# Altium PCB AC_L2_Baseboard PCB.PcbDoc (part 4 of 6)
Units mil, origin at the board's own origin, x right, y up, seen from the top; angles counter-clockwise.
Board outline 7290 x 7055 mil, 4 copper layers (Top Layer, Layer 1, Layer 2, Bottom Layer), stack 70.356 mil thick; 510 components, 285 nets, 1364 pads, 522 vias.
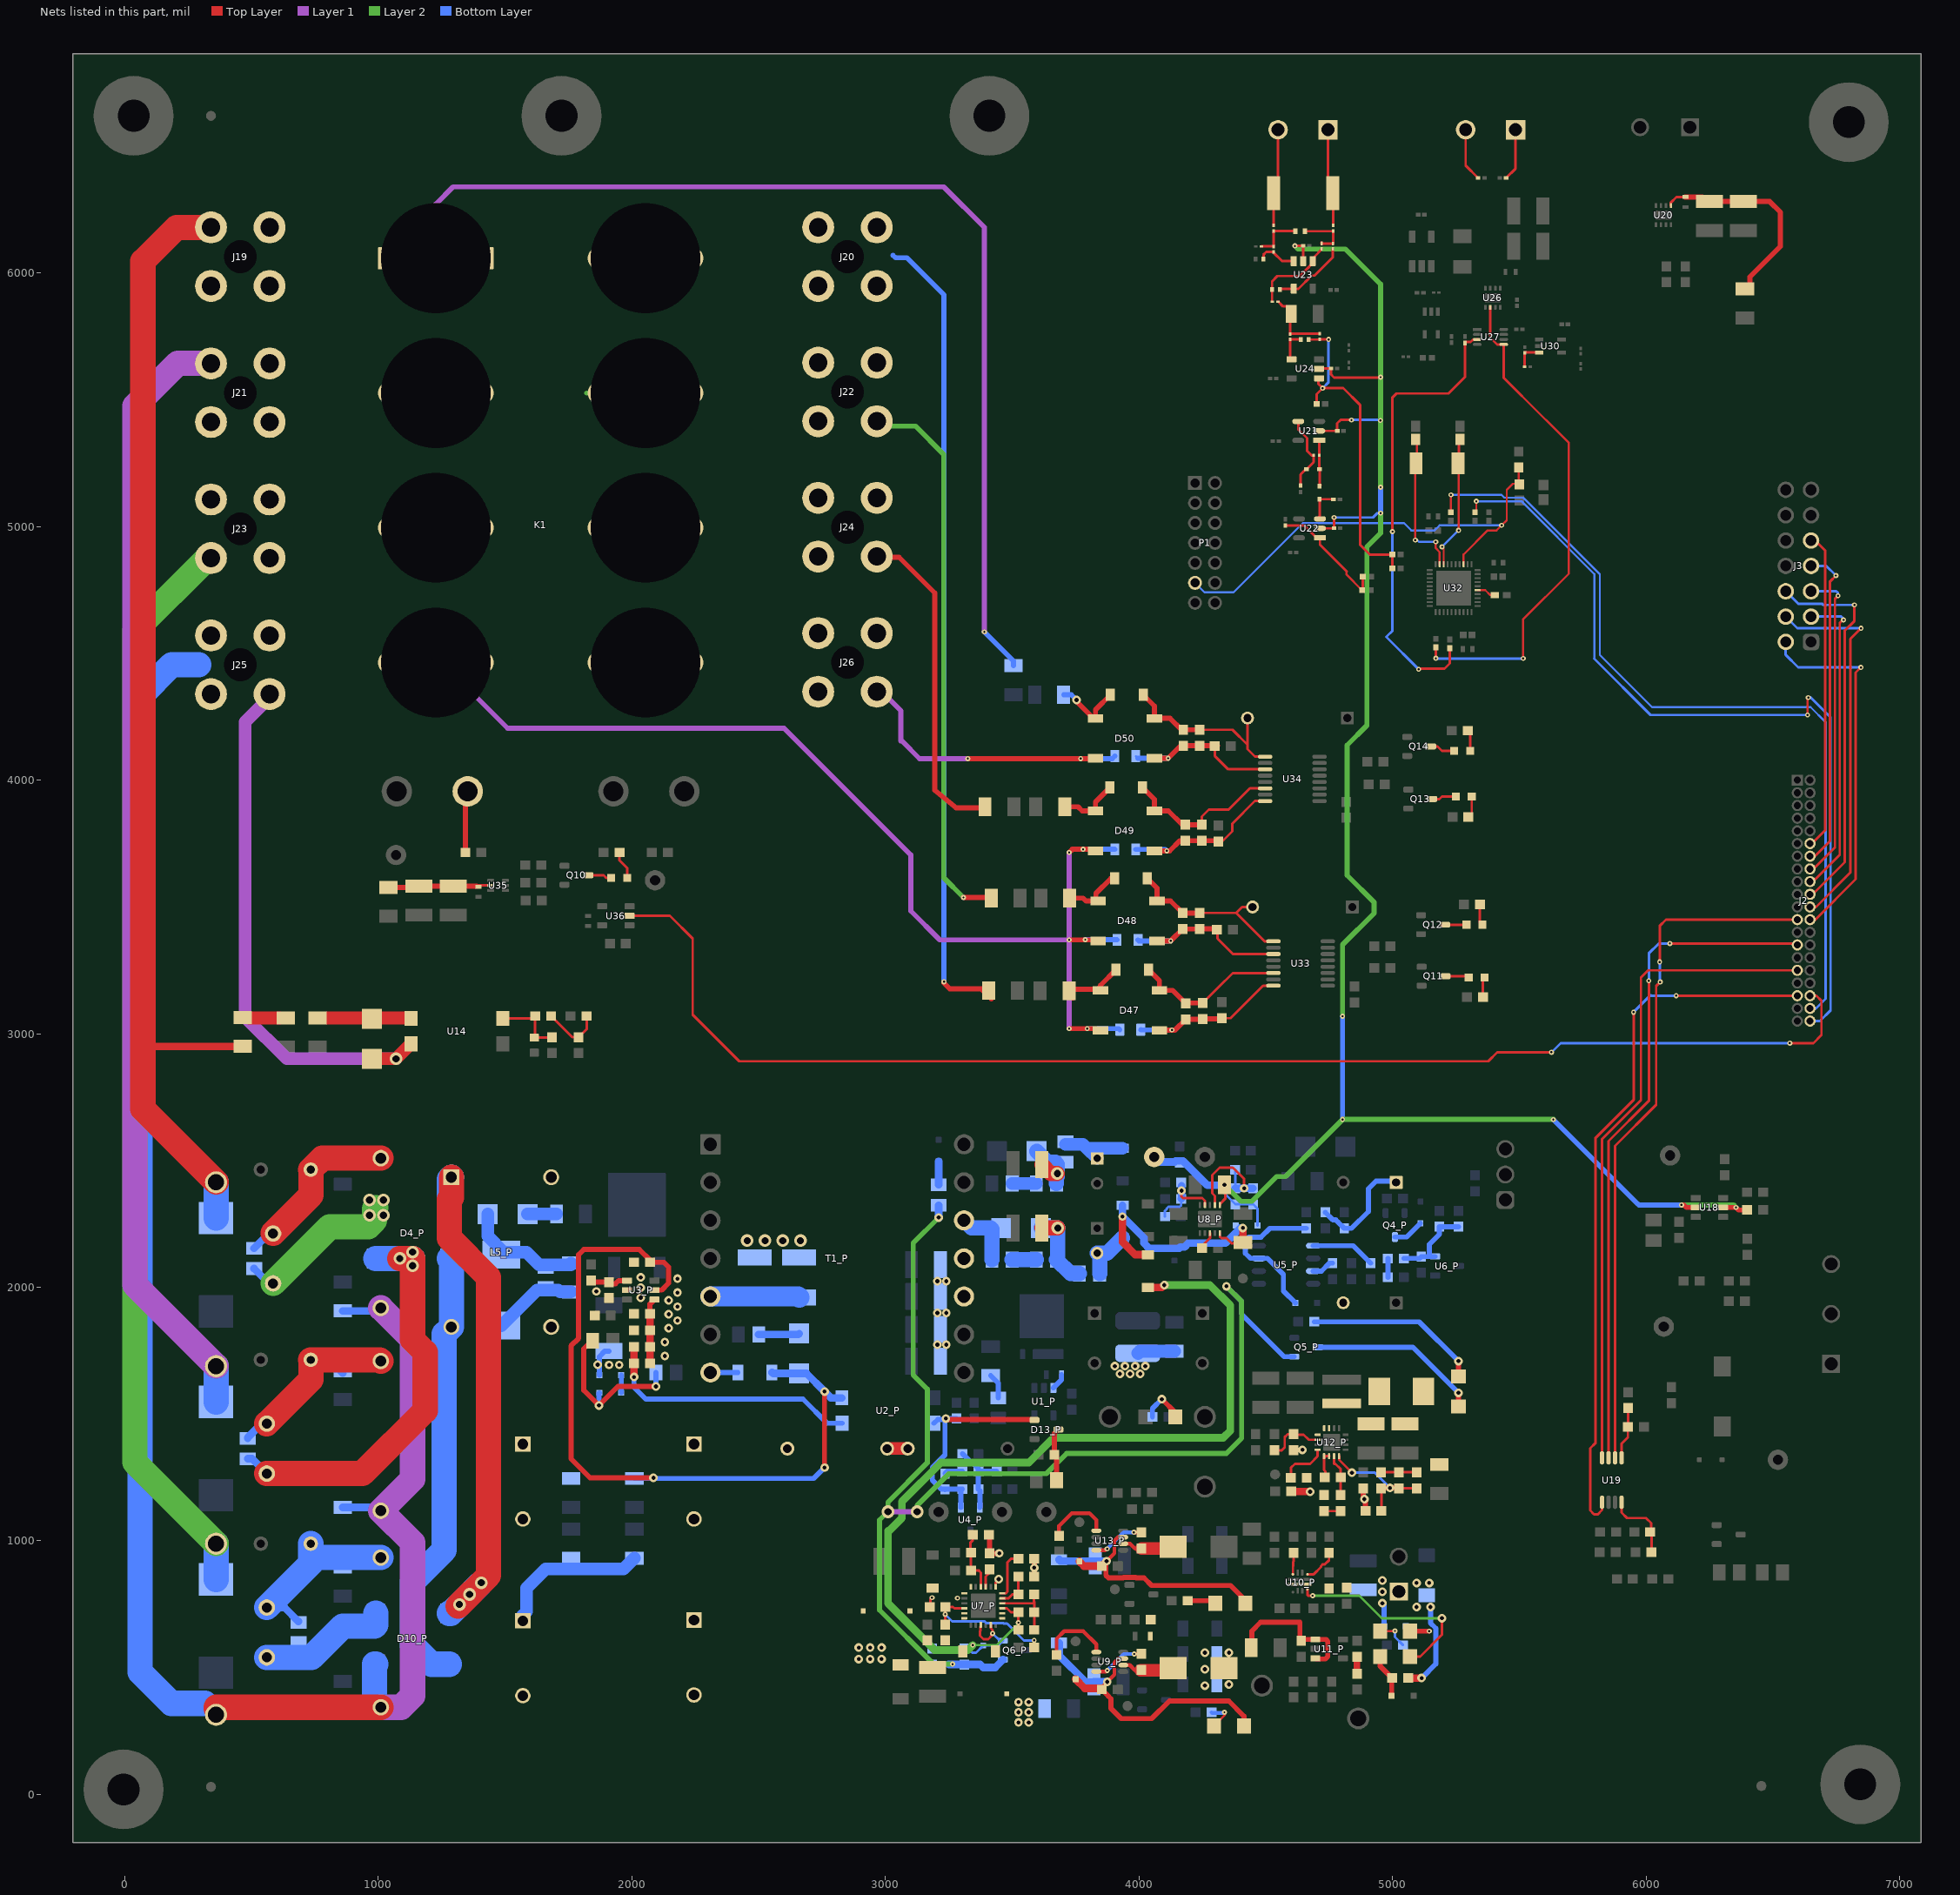
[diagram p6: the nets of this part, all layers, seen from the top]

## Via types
v1: diameter 34, hole 16, Top Layer to Bottom Layer, tented both sides, 231 vias
v2: diameter 20, hole 8, Top Layer to Bottom Layer, tented both sides, 209 vias
v3: diameter 50, hole 28, Top Layer to Bottom Layer, tented both sides, 48 vias
v4: diameter 19.68, hole 7.87, Top Layer to Bottom Layer, 29 vias
v5: diameter 24, hole 12, Top Layer to Bottom Layer, 5 vias

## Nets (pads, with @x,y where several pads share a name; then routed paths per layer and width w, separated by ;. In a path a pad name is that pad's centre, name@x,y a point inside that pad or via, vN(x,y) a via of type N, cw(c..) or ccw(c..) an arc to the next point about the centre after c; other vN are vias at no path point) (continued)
-12Va: C58_P.2 C59_P.1 C61_P.1 C100.1 C117.2 C118.2 C119.2 C120.2 D24_P.1 R54_P.2 TP12_P.1 U8_P.6 U18.2 U18.5 U21.2 U22.2 U23.2 U24.2 | length 7930.8
  Top Layer w10: U8_P.6@4319.37,2324.12 4319.88,2324.12 4320,2324 4320,2329 4340,2349 4340,2401.09 v1(4337.09,2404) ; v2(4615,6107) C117.2@4647.83,6106.96 ; C117.2@4647.83,6106.96 4647.91,6106.87 4647.91,6047.22 U23.2@4648,6047.13 ; U24.2@4707.79,5623.4 C118.2@4757.59,5623.4 4757.59,5600.41 4770,5588 4952,5588 v2(4953,5589) ; U21.2@4710.95,5377.4 C119.2@4782.61,5377.4 4782.08,5377.93 4782.08,5407.08 4795.44,5420.44 v2(4838,5420.44) ; U22.2@4713.91,4992.98 4766.95,4992.98 4769.57,4995.59 v2(4769.56,5035.96) ; v2(6140,2325) v2@6149,2325
  Top Layer w20: v2@6149,2325 6159,2315 U18.5@6195.87,2315 ; U18.2@6304.13,2315 v2(6355,2315) 6365,2305 C100.1@6398.5,2305
  Layer 2 w20: v1(4337.09,2404) 4402.09,2339 4445,2339 4543,2437 4578,2437 v2(4803,2662) v2@5635,2662 ; v2(4615,6107) 4627.5,6094.5 4814.5,6094.5 4953,5956 v2(4953,5589) v2(4953,5155) ; v2(4803,3069) 4803,3351 4928,3476 4928,3518 4821,3625 4821,4138 4899,4216 4899,4920 4953,4974 v2(4953,5053) ; v2(6140,2325) 6345,2325 v2(6355,2315)
  Bottom Layer w10: v1(4337.09,2404) 4337.09,2402.54 4337.09,2370.42 R54_P.2@4380,2327.5 C58_P.2@4450,2327.5 4468.31,2309.2 D24_P.1@4468.31,2244 ; v2(4769.56,5035.96) 4922.96,5035.96 4940,5053 v2(4953,5053) ; v2(4838,5420.44) 4950.56,5420.44 v2(4952.47,5418.53)
  Bottom Layer w20: v2(4803,2662) v2(4803,3069) ; v2(4953,5053) v2(4953,5155) ; v2(5634.5,2661.5) 5967,2329 ; 5968,2329 5972,2325 v2(6140,2325)
  Bottom Layer w30: TP12_P.1@4060,2514 4080,2494 4140,2494 4145,2499 4173.27,2499 4269.72,2402.54 v1@4337.09,2402.54
-14V: C53_P.1 D5_P.2 D8_P.2 D24_P.2 U8_P.5 | length 1007.3
  Top Layer w10: U8_P.5@4319.37,2213.88 4319.37,2199.63 4325,2194 4345,2194 4365,2174 C53_P.1@4407.09,2174 ; C53_P.1@4410,2176.91 C53_P.1@4410,2189
  Top Layer w30: v1(3935,2279) 3935,2179 3985.53,2128.47 D5_P.2@4035,2128.47 ; C53_P.1@4410,2189 v1(4410,2234)
  Bottom Layer w30: D8_P.2@3935,2323.47 v1(3935,2279) 3936.08,2279 4020,2195.08 4020,2174 4040,2154 4158.61,2154 4163.48,2158.87 4179.87,2158.87 4195,2174 4341.02,2174 4401.02,2234 v1(4410,2234)
-14V_INV: C52_P.1 C54_P.1 D5_P.1 D22_P.2 R51_P.2 U7_P.15 | length 3473.2
  Top Layer w10: U7_P.15@3460.8,734.16 3479.82,734.16 3494.98,719 R51_P.2@3524.5,719 v2(3524.5,677.54) C52_P.1@3524.5,649
  Top Layer w30: D5_P.1@4035,1999.53 4035.53,1999 4090,1999 v1(4100,2009)
  Layer 2 w10: v2(3345,589) 3440,589 3524.5,673.5 v2(3524.5,677.54)
  Layer 2 w30: v2(3345,589) 3325,569 3195,569 3010,754 3010,1040 3015,1040 3065,1090 3065,1155 3219,1309 3566.02,1309 3664.02,1407 4333,1407 4360,1434 4360,1929 4280,2009 v1(4100,2009)
AC_Sense+: J16.1 R139.1 R143.2 | length 385.6
  Top Layer w10: J16.1@4745.56,6564.96 4745.56,6333.54 R143.2@4763.98,6315.12 4765.56,6313.54 R139.1@4765.56,6187.68
AC_Sense-: J16.2 R143.1 R145.1 | length 384.8
  Top Layer w10: R145.1@4530.56,6187.68 4530.56,6313.98 R143.1@4531.7,6315.12 4548.71,6332.13 J16.2@4548.71,6564.96
AC_SENSING_A: C130.2 R135.2 R144.1 R175.1 R178.1 U24.1 | length 1323.5
  Top Layer w10: C130.2@4669.79,5737.81 4712.73,5737.81 4712.81,5737.89 4712.89,5738 v2(4748,5738) ; R144.1@4700.72,5483.4 4700.72,5522.12 v2(4724.56,5545.96) ; U24.1@4707.79,5586 4707.79,5562.73 v2(4724.56,5545.96) ; R178.1@4998.94,4834.72 R175.1@4998.94,4889.72 4911.28,4889.72 4872,4929 4872,5480 4806.04,5545.96 v2(4724.56,5545.96)
  Bottom Layer w10: v2(4724.56,5545.96) 4748,5569.4 v2(4748,5738)
AC_SENSING_B: R138.2 R179.1 R180.1 U22.1 | length 489.9
  Top Layer w8: 4819,4823.23 4819,4810.27 R180.1@4880.27,4749 R180.1@4882.17,4747.1
  Top Layer w10: R138.2@4578.04,5003.76 4652.48,5003.76 4700.66,4955.57 U22.1@4713.91,4955.57 4713.91,4928.31 4819,4823.23 ; R180.1@4882.17,4747.1 R179.1@4882.17,4803
ADC_SPI_CS: J2.35 U19.1 | length 2800.9
  Top Layer w10: U19.1@5826.61,1152.4 5826.61,1121.61 5810,1105 5795,1105 5780,1120 5780,1365 5800,1385 5800,2588 5951,2739 v2(5951,3085) ; v2(6119,3150) J2.35@6597,3150
  Bottom Layer w10: v2(5951,3085) 6018,3152 6020,3150 v2(6119,3150)
ADC_SPI_DIN: J2.23 U19.6 | length 2722.4
  Top Layer w10: U19.6@5877.8,1327.6 5877.8,2557.8 6040,2720 6040,3188 v2(6056,3204) ; v2@6054,3286 6054,3425 6079,3450 J2.23@6597,3450
  Bottom Layer w10: v2(6054,3283) 6054,3206 v2(6056,3204)
ADC_SPI_DOUT: J2.27 U19.7 | length 2665.8
  Top Layer w10: U19.7@5852.2,1327.6 5852.2,2576.2 6011,2735 6011,3212 v2(6011,3209) ; v2(6094,3356) 6591,3356 J2.27@6597,3350
  Bottom Layer w10: v2(6011,3209) 6011,3317 6050,3356 v2(6094,3356)
ADC_SPI_SCLK: J2.31 U19.8 | length 2586.5
  Top Layer w10: U19.8@5826.61,1327.6 5826.61,2584.61 5980,2738 5980,3222 6008,3250 J2.31@6597,3250
AGND1: C49_P.1 C55_P.2 C56_P.1 C57_P.2 C62_P.2 D25_P.2 NT1_P.2 Q6_P.2 R48_P.2 R57_P.1 U7_P.9 U7_P.11 U7_P.19 | length 768.9
  Top Layer w10: C55_P.2@3174.5,739 3177,739 3177,769 v2(3184,776) ; U7_P.9@3376,669.04 U7_P.9@3376.16,669.2 3376.16,662.31 3375.5,661.65 3375.5,646.85 3373.13,644.47 3373.13,625.53 3386.53,612.13 3405.47,612.13 3418.87,625.53 3418.87,630.87 v2(3423,635) 3423,647.62 3417.42,653.21 3417.42,653.58 3415.53,655.47 U7_P.11@3415.53,669.2 ; U7_P.19@3435.21,818.8 3435.21,837.21 v1(3447,849)
  Top Layer w20: R48_P.2@3407.5,1024 3411,1020.5 C56_P.1@3411,950.5 3448.5,950.5 v1(3449,951) ; C49_P.1@3587.5,859 C57_P.2@3587.5,929
  Bottom Layer w10: C62_P.2@3185,575.5 R57_P.1@3311,575.5 3326.16,575.5 3335.53,566.13 3335.87,566.13 3343,559 3357.69,559 D25_P.2@3386,587.31 3444.66,587.31 Q6_P.2@3463.76,606.4 3451.6,606.4 v2(3423,635)
  other v1: 3587,894
  other v2: 3284.21,774.5
AGND2: C82_P.1 C91_P.2 C92_P.2 C93_P.1 NT2_P.1 R77_P.1 R78_P.1 R201_P.1 U12_P.5 U12_P.6 | length 306.9
  Top Layer w10: C82_P.1@4610,1357.5 4643.5,1357.5 v1(4645,1359) ; C91_P.2@4732.2,1249 4735,1251.8 4735,1274 4730,1279 4730.41,1326.99 4737.3,1333.88 U12_P.6@4750.16,1333.88
  Top Layer w20: R78_P.1@4885,1207.5 4885,1169 4893.5,1160.5 R77_P.1@4893.5,1119
  Top Layer w30: R201_P.1@4600,1195 4674,1195 v1(4675,1194)
  other v1: 4889.25,1164.75
AM62_R_ENABLE: J2.36 U36.2 | length 5345.9
  Top Layer w10: U36.2@1990.61,3465.04 2149.96,3465.04 2240,3375 2240,3075 2423.5,2891.5 5377.5,2891.5 5413,2927 v2(5627,2927) ; v2(6567,2963) 6660,2963 6692.08,2995.08 6692.08,3129.92 6672,3150 J2.36@6647,3150
  Bottom Layer w10: v2(5627,2927) 5663,2963 v2(6567,2963)
EM_GPIO1: J2.12 J3.9 | length 1231.2
  Top Layer w10: J2.12@6647,3750 6654,3750 6706,3802 6706,4906 J3.9@6673,4939
EM_M0_EN_GPIO: J2.14 J3.7 | length 1274.1
  Top Layer w10: J2.14@6647,3700 6666,3700 6726,3760 6726,4784 v2(6749,4807)
  Bottom Layer w10: J3.7@6651,4845 6711,4845 v2(6749,4807)
EM_P1_A_GPIO: J2.18 J3.3 | length 1230.6
  Top Layer w10: J2.18@6647,3600 6658,3600 6764,3706 6764,4620 6776,4632 v2(6779,4632)
  Bottom Layer w10: J3.3@6651,4645 6770,4645 6779,4636 v2(6779,4632)
EM_P2_R_GPIO: J2.16 J3.5 | length 1250.1
  Top Layer w10: J2.16@6647,3650 6660,3650 6745,3735 6745,4715 v2(6757,4727)
  Bottom Layer w10: J3.5@6651,4745 6750,4745 6757,4738 v2(6757,4727)
EM_UART_GPIO: J2.20 J3.6 | length 1513.3
  Top Layer w10: J2.20@6647,3550 6653,3556 6664,3556 6784,3676 6784,4590 6822,4628 v2(6822,4691)
  Bottom Layer w10: J3.6@6551,4745 6600,4696 6694,4696 6699,4691 v2(6822,4691)
EM_UART_RX: J2.22 J3.4 | length 1511.8
  Top Layer w10: J2.22@6647,3500 6670,3500 6806,3636 6806,4557 v2(6848,4599)
  Bottom Layer w10: J3.4@6551,4645 6597,4599 v2(6848,4599)
EM_UART_TX: J2.24 J3.2 | length 1457.9
  Top Layer w10: J2.24@6647,3450 6668,3450 6827,3609 6827,4424 v2(6847.5,4444.5)
  Bottom Layer w10: J3.2@6551,4545 6551,4494 6600.5,4444.5 v2(6847.5,4444.5)
FF_Q+: R184.1 U26.6 U27.5 | length 1991.4
  Top Layer w8: 5510.56,5514.96 5695.56,5329.96 5695.56,4814.96 5515.56,4634.96 v2(5515.56,4479.96)
  Top Layer w10: v2(5171.03,4480.43) R184.1@5171.03,4523.94 ; U26.6@5385.87,5864.96 5385.87,5745.13 5412.57,5718.43 U27.5@5438.76,5718.43 5438.76,5586.76 5510.56,5514.96
  Bottom Layer w10: v2(5171.03,4480.43) 5171.5,4479.96 v2(5515.56,4479.96)
FF_Q-: R154.1 R187.1 U27.3 | length 1835.8
  Top Layer w10: v2(5000,4980) 5000,5509.4 5015.56,5524.96 5220.56,5524.96 5285.56,5589.96 5285.56,5725.13 5288.45,5728.02 5308.45,5728.02 5318.22,5737.8 5334.03,5737.8 U27.3@5334.36,5738.12 ; v2(5103.06,4437.46) 5105.56,4439.96 5205.56,4439.96 5226.03,4460.43 R187.1@5226.03,4520.67
  Bottom Layer w10: v2(5000,4980) 5000,4589.41 4975.56,4564.96 v2@5103.03,4437.49
FluxGate+: J17.1 R151.2 | length 205.4
  Top Layer w10: R151.2@5448.35,6374.96 5485.56,6412.17 J17.1@5485.56,6564.96
FluxGate-: J17.2 R152.2 | length 210.3
  Top Layer w10: J17.2@5288.71,6564.96 5288.71,6424.02 R152.2@5337.76,6374.96
Fly_ON: C62_P.1 D25_P.1 Q5_P.1 Q6_P.1 R56_P.2 R57_P.2 | length 4978.5
  Layer 1 w20: v3(3010,1115) v3(3125,1115)
  Layer 2 w20: v3(3125,1115) 3125,1140 3250,1265 3635,1265 3715,1345 4345,1345 4405,1405 4405,1944 v1(4345,2004) ; v1(3210,2275.02) 3110,2175.02 3110,1654 3165,1599 3165,1308.07 3010,1153.07 v3(3010,1115) 2977.13,1082.13 2977.13,726.87 3190,514 v2(3265,514)
  Bottom Layer w20: C62_P.1@3185,512.5 3247.5,512.5 3248.99,514 ; v1(4345,2004) 4405,1944 4405,1894 4572.4,1726.6 Q5_P.1@4612.76,1726.6
  Bottom Layer w30: v1(3210,2275.02) R56_P.2@3210,2324 ; 3248.99,514 3250.49,512.5 R57_P.2@3311,512.5 3374.19,512.5 D25_P.1@3386,500.69 3432.85,500.69 Q6_P.1@3463.76,531.6
GND: C2_P.2 C6_P.2 C7_P.2 C16_P.2 C17_P.2 C30_P.2 C32_P.2 C34_P.2 C200_P.1 D16_P.1 L5_P.3 R31_P.1 R35_P.1 R40_P.1 T1_P.7 U3_P.5 | length 228.1
  Bottom Layer w20: D16_P.1@1871.69,1654 1871.69,1726.69 1893.45,1748.45 R35_P.1@1910,1748.45 ; T1_P.7@2310,1664 C30_P.2@2418.07,1664
  other v1: 1910,1694 1950,1694 1864.88,1694.83 2130,1729 2130,1784 2145,1839 2180,1869 2145,1894 2180,1924 2145,1949 2035,1959 2180,1979 1860,1984 2035,1999 2180,2034 2035,2039
  other v3: 2455,2184 2525,2184 2595,2184 2665,2184
"GPIO AC Fault": J2.40 R189.1 | length 3341.5
  Top Layer w8: R189.1@5325.56,5056.69 5330.56,5061.69 v2(5330.56,5099.96)
  Top Layer w10: v2(6637,4257) 6637,4323 v2(6640,4326)
  Bottom Layer w8: v2(5330.56,5099.96) 5509.04,5099.96 5796,4813 5796,4479
  Bottom Layer w10: 5796,4479 6018,4257 v2(6637,4257) ; v2(6640,4326) 6650,4326 6728,4248 6728,3092 6686,3050 J2.40@6647,3050
"GPIO DC Fault": J2.38 R190.1 | length 3272.6
  Top Layer w8: R190.1@5230.56,5056.69 5228.56,5058.69 5230.56,5060.69 v2(5230.56,5124.96)
  Bottom Layer w8: v2(5230.56,5124.96) 5430.04,5124.96 5441.04,5113.96 5516.25,5113.96 5818,4812.21 5818,4494 6024,4288 6649,4288 6708,4229
  Bottom Layer w10: J2.38@6647,3100 6670,3100 6708,3138 6708,4229
LINE1_IN: C95.1 F1_P.2 J19.1 K1.1 R204.2 TP1_P.1 | length 8856.5
  Top Layer w30: 71.5,2950 C95.1@465,2950
  Top Layer w100: J19.1@340,6180 205,6180 71.5,6046.5 71.5,2950 71.5,2703.5 TP1_P.1@360,2415
  Layer 1 w20: K1.1@1226.61,6058.31 1226.61,6271.61 1295,6340 3230,6340 3390,6180 v2(3390,4585)
  Bottom Layer w20: v2(3390,4585) 3505,4470 R204.2@3505,4451.65
  Bottom Layer w100: F1_P.2@360,2273.06 TP1_P.1@360,2414
LINE1_OUT: J20.1 K1.12 R193.2 | length 3398.7
  Top Layer w20: v2(3231.05,3205) 3231.05,3200 3253.94,3177.11 3377.59,3177.11 R193.2@3417.4,3137.3
  Bottom Layer w20: K1.12@1846.69,6058.31 K1.12@2053.39,6058.31 ; 3030,6070 3040,6060 3085,6060 3231.05,5913.95 v2(3231.05,3205)
LINE2_IN: F2_P.2 J21.1 K1.2 TP2_P.1 | length 4428
  Layer 1 w100: J21.1@339.46,5644.05 209.05,5644.05 40,5475 40,2010 TP2_P.1@360,1690
  Bottom Layer w100: F2_P.2@360,1548.06 TP2_P.1@360,1689
LINE2_OUT: J22.1 K1.11 R196.2 | length 2413.8
  Top Layer w20: v2(3307.7,3537.3) R196.2@3422.4,3537.3
  Layer 2 w20: 1821.81,5526.81 K1.11@2053.39,5526.81 ; J22.1@2988.35,5396.12 3118.88,5396.12 3230,5285 3230,3615 v2(3307.7,3537.3)
LINE3_IN: F3_P.2 J23.1 K1.3 TP3_P.1 | length 4280.1
  Layer 2 w100: J23.1@327.5,4877.5 40,4590 40,1310 TP3_P.1@360,990
  Bottom Layer w100: F3_P.2@360,848.06 TP3_P.1@360,989
LINE3_OUT: J24.1 K1.10 R201.2 | length 1270.7
  Top Layer w20: J24.1@2987,4879 3054.33,4879 3195,4738.33 3195,3960 3280.01,3890.49 3278.3,3890.31 R201.2@3392.83,3890.31
MIRROR_IN: K1.6 R217.1 | length 244.7
  Top Layer w20: R217.1@1343.5,3715 1343.5,3946.85 K1.6@1352.6,3955.94
N_IN: C9_P.2 C15_P.2 C20_P.2 D10_P.3 D34.2 D47.4 D48.4 D49.4 J25.1 K1.4 R7_P.1 R12_P.1 R19_P.1 R800.1 R801.1 R802.1 TP5_P.1 U14.2 | length 14180.7
  Top Layer w20: v2(3725,3020) v2(3796,3020) D47.4@3831.75,3020 ; v2(3725,3370) D48.4@3826.59,3370 ; v2(3725,3715) 3737.3,3727.3 v2(3779.93,3727.3) D49.4@3822.56,3727.3
  Top Layer w50: D34.2@975,2901.26 v3(1069.67,2901.26) U14.2@1128.41,2960
  Top Layer w100: TP5_P.1@360,339 360,343.72 C20_P.2@1010,343.72
  Layer 1 w20: K1.4@1226.61,4463.82 1251.18,4463.82 1510,4205 2600,4205 3100,3705 3100,3484 3214,3370 v2(3725,3370) ; v2(3725,3020) v2(3725,3370) ; v2(3725,3715) v2(3725,3370)
  Layer 1 w50: J25.1@570,4325 475,4230 475,3065 638.74,2901.26 v3(1069.67,2901.26)
  Layer 1 w100: C20_P.2@1010,343.72 1089.72,343.72 1135,389 1135,993.72 C15_P.2@1010,1118.72 1135,1243.72 1135,1793.72 C9_P.2@1010,1918.72
  Bottom Layer w20: v2(3779.93,3727.3) 3904.36,3727.3 R802.1@3904.66,3727 ; v2(3788,3371) 3912.66,3371 R801.1@3913.66,3370 ; v2(3796,3020) 3920.66,3020 R800.1@3924.66,3016
  Bottom Layer w30: R19_P.1@860,331.91 873.19,318.72 C20_P.2@1010,318.72 ; R12_P.1@860,1131.91 996.81,1131.91 C15_P.2@1010,1118.72 ; R7_P.1@860,1906.91 998.19,1906.91 C9_P.2@1010,1918.72
  Bottom Layer w100: 291.38,4455 185,4455 60,4330 60,482.77 183.68,359.09 315.91,359.09 ; D10_P.3@990.32,513.61 985.39,513.61 985,514 985,368.72 C20_P.2@1010,343.72
N_OUT: D50.4 J26.1 K1.9 R803.2 | length 1142.9
  Top Layer w20: v2(3325,4085) v2(3770,4085) 3827.6,4085 D50.4@3828.86,4086.26
  Layer 1 w20: J26.1@3000,4335 3061.1,4273.9 3061.1,4156.1 3060,4155 3065,4155 3135,4085 v2(3325,4085)
  Bottom Layer w20: v2(3770,4085) 3894.66,4085 R803.2@3904.66,4095
NetC1_P_1: C1_P.1 C5_P.1 D2_P.1 L1_P.1 | length 256.6
  Top Layer w60: C5_P.1@3617.09,2484 3652.09,2449 v3(3678.31,2449)
  Bottom Layer w60: D2_P.1@3596.81,2537.15 3639.96,2494 3670,2494 3678.31,2485.69 v3(3678.31,2449) 3678.31,2437.54 3675,2434.24 C1_P.1@3675,2409
NetC1_P_2: C1_P.2 R1_P.2 | length 95
  Bottom Layer w50: R1_P.2@3500,2409 C1_P.2@3595,2409
NetC2_P_1: C2_P.1 C3_P.2 | length 81.3
  Top Layer w50: C2_P.1@3006.85,1364 C3_P.2@3088.15,1364
NetC4_P_1: C4_P.1 D3_P.2 L1_P.2 | length 288.4
  Bottom Layer w50: L1_P.2@3710,2564 3779.21,2564 3794.74,2548.47 ; C4_P.1@3835,2508.21 3794.74,2548.47 ; D3_P.2@3935,2548.47 3794.74,2548.47
NetC6_P_1: C6_P.1 C7_P.1 C8_P.1 C13_P.1 C14_P.1 D6_P.2 L5_P.2 R4_P.2 R5_P.2 T1_P.5 | length 687.7
  Bottom Layer w50: D6_P.2@1485,1848.51 1625.49,1989 1710,1989 1717.09,1981.91 R4_P.2@1760,1981.91
  Bottom Layer w80: T1_P.5@2310,1964 2656.26,1964 C7_P.1@2660,1960.26
NetC8_P_2: C8_P.2 D6_P.1 D9_P.1 R4_P.1 | length 469.5
  Bottom Layer w50: D9_P.1@1431.26,2289 1431.26,2202.25 1494.51,2139 1585,2139 1635,2089 1760,2089 R4_P.1@1760,2096.09
NetC9_P_1: C9_P.1 L2_P.1 R2_P.2 R3_P.1 RT1_P.2 | length 859.7
  Top Layer w100: L2_P.1@585,2212.43 585,2214 735,2364 735,2462.43 RT1_P.2@733.43,2464 778.7,2509.28 C9_P.1@1010,2509.28
  Bottom Layer w30: R3_P.1@510,2154 568.43,2212.43 L2_P.1@585,2212.43 ; R2_P.2@860,2511.24 1008.03,2511.24 C9_P.1@1010,2509.28
NetC10_P_2: C10_P.2 C11_P.1 D7_P.2 L3_P.1 | length 369
  Top Layer w60: C10_P.2@3617.09,2234 v3(3680,2234)
  Bottom Layer w60: D7_P.2@3613.74,2234 v3(3680,2234) 3680,2114 C11_P.1@3675,2109 3730,2054 L3_P.1@3765,2054
NetC11_P_2: C11_P.2 R6_P.2 | length 95
  Bottom Layer w60: R6_P.2@3500,2109 C11_P.2@3595,2109
NetC12_P_2: C12_P.2 D8_P.1 L3_P.2 | length 209.7
  Bottom Layer w60: L3_P.2@3845,2054 3845,2124.79 C12_P.2@3835,2134.79 3875.26,2134.79 D8_P.1@3935,2194.53
NetC13_P_2: C13_P.2 C14_P.2 C16_P.1 C17_P.1 R8_P.1 R13_P.2 | length 587.4
  Bottom Layer w50: C16_P.1@1570,706.64 1585,721.64 1585,814 1660,889 1967.09,889 R13_P.2@2010,931.91
NetC15_P_1: C15_P.1 L4_P.1 R9_P.2 R10_P.1 RT2_P.2 | length 852.8
  Top Layer w100: L4_P.1@560,1462.43 735,1637.43 735,1712.43 RT2_P.2@733.43,1714 1005.28,1714 C15_P.1@1010,1709.28
  Bottom Layer w30: R10_P.1@485,1404 485,1407.31 540.12,1462.43 L4_P.1@560,1462.43 ; RT2_P.2@733.43,1714 807.24,1714 R9_P.2@860,1661.24
NetC19_P_1: C19_P.1 U1_P.3 | length 65.4
  Bottom Layer w20: U1_P.3@3662.4,1603.13 3695,1635.73 C19_P.1@3695,1655
NetC20_P_1: C20_P.1 L6_P.1 R15_P.1 R16_P.2 RT3_P.2 | length 760.8
  Bottom Layer w30: L6_P.1@560,737.43 629.88,737.43 R15_P.1@685,682.31
  Bottom Layer w100: L6_P.1@560,737.43 733.43,910.85 RT3_P.2@733.43,965.57 ; RT3_P.2@733.43,989 RT3_P.2@733.43,965.57 ; C20_P.1@1010,934.28 764.72,934.28 RT3_P.2@733.43,965.57
NetC21_P_1: C21_P.1 C22_P.1 C23_P.1 C24_P.1 L7_P.1 R200_P.1 T1_P.10 T1_P.11 | length 149.7
  Bottom Layer w50: L7_P.1@3996.02,1739 L7_P.1@3995,1740.02 4002.89,1747.91 R200_P.1@4140,1747.91
  other v1: 3925,1659 3965,1659 4005,1659 3905,1689 3945,1689 3985,1689 4025,1689 3205,1774 3240,1774 3205,1899 3240,1899 3205,2024 3240,2024
NetC27_P_1: C27_P.1 R22_P.1 | length 100.3
  Bottom Layer w20: R22_P.1@3415,1651.91 3445,1621.91 C27_P.1@3445,1564
NetC28_P_1: C28_P.1 C29_P.1 D13_P.1 R24_P.2 U2_P.2 U4_P.1 | length 918.9
  Top Layer w20: v1(3238.5,1482.5) 3242.01,1479 3585.16,1479 D13_P.1@3587.76,1476.4
  Bottom Layer w20: U2_P.2@3191.59,1464 3206.59,1479 v1@3235,1479 ; C29_P.1@3235,1202.5 C29_P.1@3236.5,1204 ; R24_P.2@3280,1482.5 v1(3238.5,1482.5) v1@3235,1479 ; U4_P.1@3297.6,1131.24 3297.6,1198.09 C28_P.1@3303.5,1204 C29_P.1@3236.5,1204 ; v1@3235,1479 3235,1339 3185,1289 3185,1239 3220,1204 C29_P.1@3236.5,1204
NetC28_P_2: C28_P.2 R27_P.1 R29_P.2 R32_P.2 U4_P.2 | length 317.1
  Bottom Layer w20: R32_P.2@3303.5,1344 3328.94,1318.57 3328.94,1317.9 3339.41,1307.43 3345,1307.43 3366.5,1285.93 R29_P.2@3366.5,1274 ; U4_P.2@3372.4,1131.24 3372.4,1133.4 3373,1134 3373,1197.5 C28_P.2@3366.5,1204 R29_P.2@3366.5,1274 ; R27_P.1@3438.5,1274 R29_P.2@3366.5,1274
NetC29_P_2: C29_P.2 R29_P.1 | length 72
  Bottom Layer w20: C29_P.2@3235,1265.5 3243.5,1274 R29_P.1@3303.5,1274
NetC30_P_1: C30_P.1 C32_P.1 D12_P.1 R17_P.1 U2_P.4 U3_P.2 | length 3086.9
  Top Layer w20: v1(2085,1249) 1835,1249 1760,1324 1760,1769 1790,1799 1790,2129 1810,2149 2030,2149 2071.5,2107.5 C32_P.1@2071.5,2099 2126,2099 2145,2080 2145,2016.32 2117.68,1989 U3_P.2@2089.13,1989 ; v1(2760,1289) v1(2760,1589)
  Bottom Layer w20: R17_P.1@2010,1246.09 2717.09,1246.09 v1(2760,1289)
  Bottom Layer w30: C30_P.1@2551.93,1664 2553.9,1664 2557.64,1660.26 D12_P.1@2660,1660.26 2688.74,1660.26 v1(2760,1589) 2785,1564 U2_P.4@2828.41,1564
NetC31_P_1: C31_P.1 D13_P.3 R30_P.2 | length 210
  Top Layer w20: C31_P.1@3675,1239 3675,1330.5 R30_P.2@3666.5,1339 3666.5,1423.25 D13_P.3@3682.24,1439
NetC34_P_1: C34_P.1 R33_P.1 U3_P.4 | length 153.7
  Top Layer w20: R33_P.1@1835,2020.5 C34_P.1@1910,2020.5 1916.5,2014 1935,2014 1947.4,2026.4 U3_P.4@1980.87,2026.4
NetC35_P_1: C35_P.1 R37_P.2 U2_P.3 | length 1039
  Top Layer w30: v1(2008.5,1646.5) C35_P.1@2008.5,1700 R37_P.2@2008.5,1765
  Bottom Layer w20: v1(2008.5,1646.5) 2008.5,1605.5 2055,1559 2675,1559 2770,1464 U2_P.3@2829.39,1464
NetC35_P_2: C35_P.2 C200_P.2 R37_P.1 R40_P.2 U3_P.1 | length 261
  Top Layer w20: C200_P.2@2071.5,1895 2071.5,1933.96 U3_P.1@2089.13,1951.6 2090.55,1951.6 U3_P.1@2091.02,1952.07
  Top Layer w30: C35_P.2@2071.5,1700 R37_P.1@2071.5,1765 R40_P.2@2071.5,1830 C200_P.2@2071.5,1895
NetC36_P_2: C36_P.2 C37_P.2 R39_P.2 R45_P.2 U6_P.2 | length 335.9
  Bottom Layer w20: C37_P.2@5045.2,2114 5107.2,2114 C36_P.2@5113.7,2120.5 5114.61,2121.4 5142.24,2121.4 ; U6_P.2@5167.76,2121.4 5142.24,2121.4 ; R45_P.2@5260,2239 R39_P.2@5185,2239 5185,2209 5145,2169 5145,2124.16 5142.24,2121.4
NetC37_P_1: C37_P.1 R41_P.2 | length 75
  Bottom Layer w20: R41_P.2@4982.2,2039 C37_P.1@4982.2,2114
NetC38_P_1: C38_P.1 C39_P.2 R43_P.1 R44_P.2 | length 437.5
  Bottom Layer w20: R44_P.2@4735,2295.5 4760.43,2270.06 4761.1,2270.06 4765.36,2265.81 4776.02,2265.81 4783.9,2257.94 4784.57,2257.94 R43_P.1@4810,2232.5 4838.5,2232.5 4905,2299 4905,2389 4935,2419 5009.33,2419 C38_P.1@5014.33,2414
NetC41_P_1: C41_P.1 U5_P.1 | length 254.8
  Bottom Layer w20: U5_P.1@4687.28,2164 4845.2,2164 C41_P.1@4913.7,2095.5
NetC42_P_1: C42_P.1 U5_P.3 | length 89.5
  Bottom Layer w20: U5_P.3@4687.28,2064 4720,2064 4751.5,2095.5 C42_P.1@4763.7,2095.5
NetC45_P_2: C45_P.2 R47_P.1 R48_P.1 U7_P.22 | length 242.6
  Top Layer w10: R48_P.1@3344.5,1024 3344.5,1002.5 3336,994 3336,955.5 R47_P.1@3337.5,954 C45_P.2@3337.5,884 3367.02,884 3376.16,874.87 U7_P.22@3376.16,818.8
NetC46_P_1: C46_P.1 R46_P.2 R49_P.2 U8_P.9 | length 314.1
  Top Layer w10: v1(4168,2381) 4168,2357 4173,2352 4250,2352 4260.31,2341.68 U8_P.9@4260.31,2324.12
  Bottom Layer w10: R49_P.2@4102.5,2279 4102.5,2301.31 4108.74,2307.54 4108.74,2309.74 4116.43,2317.43 4128.52,2317.43 4129.1,2318 4161,2318 4166.5,2323.5 R46_P.2@4166.5,2349
  Bottom Layer w30: R46_P.2@4166.5,2349 4168,2350.5 v1(4168,2381) C46_P.1@4168,2400
NetC49_P_2: C49_P.2 R50_P.2 U7_P.17 | length 140.1
  Top Layer w10: U7_P.17@3460.8,773.53 3485.53,773.53 3501,789 R50_P.2@3524.5,789 C49_P.2@3524.5,859
NetC50_P_1: C50_P.1 C51_P.1 L8_P.1 L9_P.2 R52_P.2 U7_P.5 U7_P.6 | length 0
  other v1: 3525,284 3565,284 3525,324 3565,324 3525,364 3565,364 2895,534 2940,534 2985,534 2895,579 2940,579 2985,579
NetC52_P_2: C52_P.2 R50_P.1 R51_P.1 U7_P.16 | length 273
  Top Layer w10: U7_P.16@3460.8,753.84 3585.84,753.84 3586,754 3586,760.46 ; C52_P.2@3587.5,649 R51_P.1@3587.5,719 3587.5,758.96 3586,760.46 ; R50_P.1@3587.5,789 3586,787.5 3586,760.46
NetC55_P_1: C55_P.1 R52_P.1 R53_P.2 U7_P.4 | length 566.8
  Top Layer w10: R52_P.1@3236,670.5 v2(3236,710.46) 3236,737.5 C55_P.1@3237.5,739 3267.02,739 3271.87,734.16 U7_P.4@3311.2,734.16 ; v2(3586.79,607.54) R53_P.2@3587.5,579
  Bottom Layer w10: v2(3236,710.46) 3263.56,682.9 3391.1,682.9 3398.25,675.75 3464.96,675.75 3466.71,674 3480,674 3546.46,607.54 v2(3586.79,607.54)
NetC56_P_2: C56_P.2 U7_P.21 | length 75
  Top Layer w10: U7_P.21@3395.84,818.8 3395.84,858.84 3411,874 C56_P.2@3411,887.5
NetC57_P_1: C57_P.1 U7_P.18 | length 187.9
  Top Layer w10: U7_P.18@3460.8,793.21 3475.21,793.21 3481,799 3481,915.02 3494.98,929 C57_P.1@3524.5,929
NetC58_P_1: C58_P.1 R54_P.1 R55_P.2 U8_P.7 | length 460.9
  Top Layer w10: U8_P.7@4299.69,2324.12 4299.69,2360.31 4289,2371 4289,2443 4289.25,2443.25 4289.3,2443.25 4318.03,2471.97 4370.53,2471.97 4415,2427.5 v1(4415,2390.5)
  Bottom Layer w10: R55_P.2@4378.5,2464 4380,2462.5 R54_P.1@4380,2390.5
  Bottom Layer w30: R54_P.1@4380,2390.5 v1(4415,2390.5) C58_P.1@4450,2390.5
NetC60_P_2: C60_P.2 U8_P.3 | length 72.9
  Top Layer w10: C60_P.2@4248.5,2154 4248.5,2162.5 4280,2194 U8_P.3@4280,2213.88
NetC63_P_1: C63_P.1 U9_P.8 | length 209
  Top Layer w15: U9_P.8@3831.85,484.67 3869.33,484.67 3870,484 3875,489 v2(3874.72,489) ; v2(3981.46,554) 4009.45,554 C63_P.1@4010,554.55 C63_P.1@4010.55,554
  Bottom Layer w15: v2(3874.72,489) 3939.72,554 v2(3981.46,554)
NetC63_P_2: C63_P.2 L13_P.1 U9_P.2 | length 212.6
  Top Layer w15: U9_P.2@3938.15,510.26 3940.31,510.26 3940.51,510.06 3963.94,510.06 3985,489 4007.44,489 C63_P.2@4010,491.56
  Top Layer w50: C63_P.2@4007.44,489 4125.55,489 L13_P.1@4134.61,498.06
NetC64_P_1: C64_P.1 C65_P.1 D30_P.2 D200_P.1 L11_P.2 U9_P.3 | length 1295.7
  Top Layer w15: C65_P.1@3853.5,418.25 3853.5,422.5 v1@3870,439 ; v1(3875,444) 3903.09,472.09 3903.09,520.3 3918.12,535.33 3937.63,535.33 U9_P.3@3938.15,535.85
  Top Layer w20: C65_P.1@3853.5,414 3853.5,407.35 3860.08,407.35 3878.94,388.49 3878.94,387.9 3889.41,377.43 3890,377.43 3890,339 3930,299 4050,299 4120,369 4354.06,369 4414.06,309 D30_P.2@4414.06,270 ; v1@3870,439 v1(3875,444)
  Top Layer w30: D200_P.1@3750,455 3786.75,418.25 C65_P.1@3853.5,418.25
  Bottom Layer w30: L11_P.2@3685,597.07 3685,549 3791.46,442.54 3823.98,442.54 3822.91,443.61 C64_P.1@3822.91,444 v1(3875,444)
NetC66_P_1: C66_P.1 C67_P.1 C81_P.1 L12_P.1 L13_P.2 R61_P.2 R62_P.2 U11_P.1 U11_P.3 | length 567.8
  Top Layer w20: L12_P.1@4442.91,579 4445,581.09 4445,644 4480,679 4635,679 4635,610.5 C81_P.1@4640,605.5 4645.91,611.4 4698.82,611.4 4737.6,611.4 4745,604 4745,544 4735,534 4701.42,534 U11_P.3@4698.82,536.6
  other v1: 4260,429 4355,434 4260,494 4260,559 4355,559
NetC73_P_1: C73_P.1 C74_P.1 D28_P.2 D29_P.1 J1_P.1 R58_P.2 R60_P.2 U10_P.5 | length 458.2
  Top Layer w30: R58_P.2@5061.5,459 v1(5115,459)
  Bottom Layer w20: v1(4960,754) 4966.69,747.31 D29_P.1@4966.69,664 ; v1(5115,459) 5171,515 5171,654.77 5150,675.77 v1(5150,739)
  other v1: 5095,739 4960,799 5095,834 5145,834 4960,844
NetC75_P_2: C75_P.2 U9_P.5 | length 285
  Top Layer w15: C75_P.2@3675,550.5 3675,614 3705,644 3780,644 3831.85,592.15 U9_P.5@3831.85,561.44
NetC76_P_1: C76_P.1 U10_P.10 | length 85
  Top Layer w10: U10_P.10@4607.44,868.53 4607.44,900.54 4608.27,901.36 4608.27,917.55 4610,919.28 C76_P.1@4610,952.5
NetC77_P_1: C77_P.1 U10_P.7 | length 138.8
  Top Layer w10: U10_P.7@4664.53,868.53 4689.53,868.53 4718.43,897.43 4718.43,900.51 4725.97,908.06 4734.06,908.06 4750,924 C77_P.1@4750,952.5
NetC78_P_2: C78_P.2 R202_P.2 | length 66
  Top Layer w25: R202_P.2@4860,476.5 C78_P.2@4860,542.5
NetC82_P_2: C82_P.2 R69_P.1 U12_P.2 | length 228.4
  Top Layer w10: R69_P.1@4535,1357.5 4563.54,1357.5 4575,1368.96 4575,1409 4586.5,1420.5 C82_P.2@4610,1420.5 4625,1420.5 4626.5,1419 4650,1419 4670.16,1398.84 U12_P.2@4704.88,1398.84
NetC83_P_1: C83_P.1 C84_P.1 C86_P.1 D32_P.1 L14_P.1 R71_P.2 R72_P.2 | length 140
  Top Layer w10: R71_P.2@4955,1270.5 R72_P.2@5025,1270.5 C86_P.1@5095,1270.5
NetC85_P_1: C85_P.1 U13_P.8 | length 210.8
  Top Layer w15: U13_P.8@3831.85,963.21 3866.21,963.21 v2@3872,969 ; v2@3874,971 v2@3872,969 ; v2(3874.38,968) 3872,968 v2@3872,969 ; v2(3980,1034) C85_P.1@4009.09,1034
  Bottom Layer w15: v2(3874.38,968) 3940.26,1033.88 3979.88,1033.88 v2(3980,1034)
NetC85_P_2: C85_P.2 L17_P.1 U13_P.2 | length 182.4
  Top Layer w15: U13_P.2@3938.15,988.8 3965.2,988.8 3985,969
  Top Layer w50: C85_P.2@4010,970.1 4128.11,970.1 L17_P.1@4134.61,976.6
NetC86_P_2: C86_P.2 R71_P.1 R72_P.1 R77_P.2 U12_P.8 | length 491
  Top Layer w10: U12_P.8@4789.53,1333.88 4790,1333.41 4790,1319 v1(4840,1269) ; R71_P.1@4955,1207.5 4956.5,1206.01 R77_P.2@4956.5,1119 ; R72_P.1@5025,1207.5 C86_P.2@5095,1207.5
  Top Layer w20: R71_P.1@4955,1207.5 4956.5,1209 v1(4990,1209) 5023.5,1209 R72_P.1@5025,1207.5
  Bottom Layer w10: v1(4840,1269) 4930,1269 v1(4990,1209)
NetC87_P_1: C87_P.1 C88_P.1 D33_P.2 D201_P.1 L16_P.2 U13_P.3 | length 1098.5
  Top Layer w15: v1(3872.6,920.3) 3903,950.7 3903,1000.49 3916.9,1014.39 U13_P.3@3938.15,1014.39
  Top Layer w20: v1(3872.6,920.3) 3870,917.7 3870,864 3880,854 3937.04,854 3939.13,856.09 3986.39,856.09 3988.47,854 4020,854 4050,824 4361.66,824 D33_P.2@4421.66,764
  Top Layer w30: D201_P.1@3765,919 3783.39,900.61 C88_P.1@3853.5,900.61 3853.5,901.2 C88_P.1@3870,917.7 ; D33_P.2@4419.06,764 D33_P.2@4421.66,764
  Bottom Layer w30: L16_P.2@3685,925.93 3690.63,920.3 C87_P.1@3827.91,920.3 v1(3872.6,920.3)
NetC91_P_1: C91_P.1 R75_P.2 U12_P.7 | length 166.9
  Top Layer w10: U12_P.7@4769.84,1333.88 4769.84,1319.16 4770,1319 4770,1304 4775,1304 4795.2,1283.8 4795.2,1249 4795.2,1180.69 R75_P.2@4795,1180.5
NetC92_P_1: C92_P.1 U12_P.4 | length 189.7
  Top Layer w10: C92_P.1@4598.5,1249 4600,1250.5 4600,1289 4615,1304 4675,1304 4704.88,1333.88 U12_P.4@4704.88,1359.47
NetC93_P_2: C93_P.2 R75_P.1 | length 65
  Top Layer w10: C93_P.2@4730,1117.5 R75_P.1@4795,1117.5
NetC94_P_2: C94_P.2 U13_P.5 | length 259.4
  Top Layer w15: C94_P.2@3685,1020.5 3685,1059 3735,1109 3750.42,1109 3750.48,1109.06 3779.52,1109.06 3779.58,1109 3805,1109 3831.85,1082.15 U13_P.5@3831.85,1039.98
NetC95_2: C95.2 R29.2 | length 120
  Top Layer w50: C95.2@490,3062.09 R29.2@610,3062.09
NetC96_1: C96.1 R82.1 R84.2 | length 239.6
  Top Layer w10: R84.2@1681.5,3070 1765,2986.5 C96.1@1790,2986.5 1821.5,3017.99 R82.1@1821.5,3070
NetC97_1: C97.1 C98.2 R84.1 U14.4 | length 288.8
  Top Layer w10: U14.4@1491.59,3060 1608.5,3060 R84.1@1618.5,3070 1618.5,2988.03 C98.2@1615,2984.53 1683.03,2984.53 C97.1@1685,2986.5
NetC110_1: C110.1 R92.2 U19.5 | length 206.9
  Top Layer w10: U19.5@5903.39,1327.6 5903.39,1383.39 5928.5,1408.5 C110.1@5928.5,1450 5930,1451.5 R92.2@5930,1523.5
NetC111_1: C111.1 R95.2 U19.4 | length 293.2
  Top Layer w10: U19.4@5903.39,1152.4 5903.39,1111.61 5925,1090 6000,1090 6020,1070 6020,1038.5 C111.1@6016.5,1035 6021.5,1030 R95.2@6021.5,955
NetC114_1: C114.1 C115.1 C116.1 F4.1 U20.1 | length 834
  Top Layer w10: U20.1@6098.19,6265.75 6098.19,6278.19 6120,6300 C116.1@6150,6300 ; C115.1@6230,6291.81 6239.92,6291.81 C115.1@6249.76,6281.97 ; F4.1@6390,5937.09 F4.1@6410,5957.09
  Top Layer w20: C116.1@6155,6300 6221.81,6300 C115.1@6230,6291.81 ; C115.1@6249.76,6281.97 C114.1@6384.33,6281.97 6488.03,6281.97 6530,6240 6530,6105 6410,5985 F4.1@6410,5957.09
NetC129_1: C129.1 R140.2 U23.4 | length 293.5
  Top Layer w10: C129.1@4556.56,5934.96 4556.56,5935.13 4559.43,5938 4629,5938 4681,5990 4692,5990 4765.11,6063.11 R140.2@4765.11,6094.92
NetC129_2: C129.2 R136.2 R141.1 U23.1 | length 342.4
  Top Layer w10: R141.1@4526.21,5886.81 4525.14,5886.81 4525.06,5886.89 C129.2@4525.06,5934.96 4525.06,5967.06 4546,5988 4634.74,5988 4670.81,6024.07 4670.81,6024.67 4685.4,6039.26 U23.1@4685.4,6047.13 4692.21,6053.94 4692.21,6064.98 4720.56,6093.32 R136.2@4720.56,6095.13
NetC130_1: C130.1 R142.2 U24.4 | length 118.3
  Top Layer w10: U24.4@4595.81,5660.19 R142.2@4595.81,5735.79 ; R142.2@4595.81,5738.13 R142.2@4595.81,5738.13 4595.89,5737.97 4638.13,5737.97 C130.1@4638.29,5737.81
NetC131_1: C131.1 D45.2 R137.1 U21.4 | length 306.8
  Top Layer w10: U21.4@4628.23,5414.8 4628.23,5383.62 4662.96,5348.9 4662.96,5298.39 4680.39,5280.96 C131.1@4689.24,5280.96 4689.24,5254.15 4661.49,5226.4 D45.2@4659.92,5226.4 4658.34,5226.4 4637.56,5205.61 R137.1@4637.56,5161.76
NetC131_2: C131.2 D45.1 D46.2 U21.1 | length 182.3
  Top Layer w10: C131.2@4710.9,5280.96 4710.98,5280.88 4710.98,5227.31 D45.1@4711.89,5226.4 ; C131.2@4710.9,5280.96 U21.1@4710.95,5340 ; D45.1@4712.56,5222.07 D46.2@4712.56,5159.94 D46.2@4716.89,5164.28
NetC132_1: C132.1 R136.1 R139.2 R140.1 | length 209
  Top Layer w10: C132.1@4654.26,6164.96 4764.49,6164.96 R139.2@4765.56,6166.02 4765.56,6116.61 4722.7,6116.61 4720.56,6118.76 R136.1@4720.56,6116.79
NetC132_2: C132.2 R145.2 R146.1 R148.1 | length 195.9
  Top Layer w10: R148.1@4482.64,6105.09 R146.1@4530.32,6105.09 ; R146.1@4530.56,6104.57 R145.2@4530.56,6166.02 4615.79,6166.02 C132.2@4616.86,6164.96
NetC133_1: C133.1 R135.1 R141.2 R142.1 | length 277.2
  Top Layer w10: R141.2@4547.87,5886.81 4549.68,5886.81 4568.25,5868.24 4583.46,5868.24 4600.11,5851.58 C133.1@4600.11,5838.79 4596.13,5834.8 R142.1@4596.13,5760.79 ; R142.1@4595.81,5759.79 4595.81,5760.71 4595.89,5760.79 R142.1@4596.13,5760.79 ; R135.1@4712.81,5760.79 R142.1@4596.13,5760.79
NetC134_1: C134.1 R146.2 U23.3 | length 157
  Top Layer w10: C134.1@4490.94,6055.04 4491,6055.1 4491,6072 4501.91,6082.91 R146.2@4530.56,6082.91 4530.56,6081.1 4564.53,6047.13 U23.3@4610.6,6047.13
NetC141_1: C141.1 R157.2 U30.3 | length 112.4
  Top Layer w10: C141.1@5521.56,5685.94 C141.1@5521.56,5685.07 ; R157.2@5521.73,5630.96 5521.64,5630.96 5521.56,5631.04 C141.1@5521.56,5685.07 ; U30.3@5578.27,5686.37 5522.86,5686.37 C141.1@5521.56,5685.07
NetC146_1: C146.1 U32.25 | length 76.5
  Top Layer w8: U32.25@5335.52,4749.53 5365.99,4749.53 5385.79,4729.72 C146.1@5403.79,4729.72
NetC147_2: C147.2 U32.39 Y1.1 | length 593
  Top Layer w8: v2(5090,4947) 5090,5227.01 5085.56,5231.46 Y1.1@5095.56,5241.46 ; Y1.1@5095.56,5249.96 Y1.1@5095.56,5241.46 ; Y1.1@5096.5,5242.4 Y1.1@5095.56,5241.46 ; v2(5170.56,4939.96) 5170.56,4914.96 5185.91,4899.61 U32.39@5185.91,4851.89
  Top Layer w10: C147.2@5090.56,5344.74 5096.5,5338.8 Y1.1@5096.5,5242.4
  Bottom Layer w8: v2(5090,4947) 5097.6,4947 5104.64,4939.96 v2(5170.56,4939.96)
NetC148_2: C148.2 U32.38 Y1.2 | length 524.4
  Top Layer w8: v2(5195.56,4919.96) 5201.66,4913.86 U32.38@5201.66,4851.89 ; v2(5260.56,4984.96) 5260.56,5241.1 Y1.2@5261.86,5242.4
  Top Layer w10: Y1.2@5261.86,5242.4 5261.86,5341.04 C148.2@5265.56,5344.74
  Bottom Layer w8: v2(5195.56,4919.96) v2(5260.56,4984.96)
NetC151_1: C151.1 P1.11 R191.1 U32.33 | length 1863.1
  Top Layer w8: U32.33@5280.4,4851.89 5280.4,4889.8 5375.56,4984.96 5410.56,4984.96 v2(5430.56,5004.96) 5450.56,5024.96 5450.56,5144.96 5474.79,5169.19 R191.1@5497.82,5169.19
  Top Layer w10: R191.1@5497.82,5169.19 C151.1@5497.82,5232.91
  Bottom Layer w8: P1.11@4221.26,4778.3 4258.82,4740.74 4373.05,4740.74 4645.88,5013.57 5045.43,5013.57 5074.04,4984.96 5166,4984.96 5186,5004.96 v2(5430.56,5004.96)
NetC156_1: C156.1 D47.1 R194.2 R197.2 R800.2 U33.16 | length 638.9
  Top Layer w10: R194.2@4326.73,3061.2 4361.2,3061.2 4489.37,3189.37 U33.16@4530.28,3189.37
  Top Layer w20: D47.1@4080.71,3013.56 4141.28,3013.56 R197.2@4184.29,3056.57 4249.37,3056.57 C156.1@4251.3,3058.5 R194.2@4321.3,3058.5
  Bottom Layer w20: R800.2@4007.34,3016 4008.34,3015 v2(4130,3015)
NetC156_2: C156.2 D47.2 D800.2 R197.1 U33.14 | length 619
  Top Layer w10: C156.2@4251.3,3121.5 4312.17,3182.36 4312.36,3182.36 4369.37,3239.37 U33.14@4530.28,3239.37
  Top Layer w20: D800.2@4038.47,3252 4080.71,3209.76 D47.2@4080.71,3171.04 4132.81,3171.04 R197.1@4184.29,3119.57 4186.22,3121.5 C156.2@4251.3,3121.5
NetC158_1: C158.1 D48.1 R198.2 R199.2 R801.2 U33.11 | length 672.8
  Top Layer w10: R198.2@4309.45,3413.5 4309.45,3375.55 4370.63,3314.37 U33.11@4530.28,3314.37
  Top Layer w20: D48.1@4071.14,3366.26 v2(4125.63,3366.26) R199.2@4172.44,3413.07 4239.02,3413.07 C158.1@4239.45,3413.5 R198.2@4309.45,3413.5
  Bottom Layer w20: R801.2@3996.34,3370 4000.08,3366.26 v2(4125.63,3366.26)
NetC158_2: C158.2 C159.2 D48.2 D801.2 R199.1 U33.9 | length 715.7
  Top Layer w10: C158.2@4239.45,3476.5 4383.5,3476.5 ; C159.2@4448.15,3500 4407.01,3500 4383.5,3476.5 ; U33.9@4530.28,3364.37 4495.63,3364.37 4383.5,3476.5
  Top Layer w20: D801.2@4032.47,3613 4071.14,3574.33 D48.2@4071.14,3523.74 4124.76,3523.74 R199.1@4172.44,3476.06 4179.88,3468.62 4179.88,3476.06 4239.02,3476.06 C158.2@4239.45,3476.5
NetC160_1: C160.1 C161.1 C162.1 F5.1 U35.5 | length 402.9
  Top Layer w10: C162.1@1391.47,3585.04 1391.79,3584.72 U35.5@1443.21,3584.72 U35.5@1442.89,3585.04
  Top Layer w20: F5.1@1040,3577.09 1155,3577.09 C160.1@1160,3582.09 C161.1@1295,3582.09 C162.1@1388.52,3582.09
NetC163_1: C163.1 D49.1 R202.2 R205.2 R802.2 U34.16 | length 661.8
  Top Layer w10: R202.2@4313.54,3758.5 4328.5,3758.5 4368.5,3798.5 4368.5,3828.5 4457.81,3917.81 U34.16@4497.72,3917.81
  Top Layer w20: D49.1@4061.14,3721.26 v2(4110,3721.26) 4121.26,3721.26 4161.36,3761.36 R205.2@4183.54,3761.36 C163.1@4248.54,3761.36 R202.2@4313.54,3761.36
  Bottom Layer w20: R802.2@3987.34,3727 4104.26,3727 v2(4110,3721.26)
NetC163_2: C163.2 D49.2 D802.2 R205.1 U34.14 | length 631.3
  Top Layer w10: C163.2@4248.54,3824.35 4248.54,3856.54 4275.66,3883.66 4353.66,3883.66 4437.81,3967.81 U34.14@4497.72,3967.81
  Top Layer w20: D802.2@4014.47,3971 4061.14,3924.33 D49.2@4061.14,3878.74 ; D49.2@4078.84,3878.74 4116.26,3878.74 4170.65,3824.35 R205.1@4183.54,3824.35 C163.2@4248.54,3824.35
NetC165_1: C165.1 D50.1 R207.2 R208.2 R803.1 U34.11 | length 658.8
  Top Layer w10: R207.2@4298.94,4135 4298.94,4096.06 4352.19,4042.81 U34.11@4497.72,4042.81
  Top Layer w20: D50.1@4061.14,4086.26 v2(4115.02,4086.26) R208.2@4170.81,4142.05 ; R208.2@4175,4135.81 C165.1@4240,4135.81 R207.2@4310,4135.81
  Bottom Layer w8: R803.1@3987.34,4095 R803.1@3996.08,4086.26
  Bottom Layer w20: R803.1@3996.08,4086.26 v2(4115.02,4086.26)
NetC165_2: C165.2 C166.2 D50.2 D803.2 R208.1 U34.9 | length 722
  Top Layer w10: C165.2@4240,4198.8 4369.35,4198.8 4428.15,4140 ; C166.2@4428.15,4245 4428.15,4140 ; U34.9@4497.72,4092.81 4457.64,4092.81 4428.15,4122.3 4428.15,4140
  Top Layer w20: D803.2@4016.47,4337 4061.14,4292.33 D50.2@4061.14,4243.74 4122.72,4243.74 R208.1@4169.85,4196.6 ; R208.1@4175,4198.8 C165.2@4240,4198.8
NetD4_P_1: D4_P.1 D10_P.1 L5_P.1 | length 2097
  Top Layer w100: L5_P.1@1288.15,2434.28 1288.15,2354.35 1279.69,2345.89 1279.69,2194.31 1435,2039 1435,864 v3@1313.92,742.92
  Bottom Layer w100: D10_P.1@1279.69,714.39 1285.39,714.39 v3@1397.5,826.5 ; D4_P.1@1279.69,2314.39 1279.69,2425.81 L5_P.1@1288.15,2434.28
  other v3: 1320,749 1360,789 1406.08,835.08
NetD4_P_2: D4_P.2 D10_P.2 L5_P.4 | length 1767.5
  Bottom Layer w100: D10_P.2@1279.69,513.61 1210.39,513.61 1135,589 1135,839 1260,964 1260,1815.57 L5_P.4@1288.15,1843.72 1288.15,2105.14 D4_P.2@1279.69,2113.61
NetD4_P_3: D4_P.3 L4_P.2 R10_P.2 | length 1642.7
  Top Layer w100: L4_P.2@560,1265.57 936.57,1265.57 1185,1514 1185,1743.72 1135,1793.72 1135,2114 v3(1085,2114)
  Bottom Layer w30: R10_P.2@485,1324 501.57,1324 L4_P.2@560,1265.57
  Bottom Layer w100: D4_P.3@990.32,2113.61 990.71,2114 1135,2114
  other v3: 1135,2085 1135,2139
NetD4_P_4: D4_P.4 L2_P.2 R3_P.2 | length 654.7
  Layer 2 w100: L2_P.2@585,2015.57 808.43,2239 960,2239 985,2264 985,2309.08 990.32,2314.39
  Bottom Layer w30: R3_P.2@510,2074 568.43,2015.57 L2_P.2@585,2015.57
  other v3: 965,2284 1020,2284 965,2344 1020,2344
NetD7_P_1: D7_P.1 R6_P.1 T1_P.12 | length 244.5
  Bottom Layer w60: T1_P.12@3310,2264 3340,2234 3415,2234 3420,2229 R6_P.1@3420,2109
NetD9_P_2: D9_P.2 R11_P.2 | length 114.2
  Bottom Layer w50: D9_P.2@1588.74,2289 R11_P.2@1702.91,2289
NetD10_P_4: D10_P.4 L6_P.2 R15_P.2 | length 528.7
  Bottom Layer w100: L6_P.2@560,540.57 736.57,540.57 860,664 985,664 990.32,669.32 D10_P.4@990.32,714.39
NetD11_P_2: D11_P.2 R20_P.1 | length 177.5
  Top Layer w20: v1(4090,1559) 4144.06,1504.94 D11_P.2@4144.06,1489
  Bottom Layer w20: R20_P.1@4053.5,1489 4053.5,1522.5 v1(4090,1559)
NetD12_P_2: D12_P.2 R23_P.1 | length 161.5
  Bottom Layer w30: R23_P.1@2500,1814 2656.26,1814 D12_P.2@2660,1817.74
NetD14_P_1: D14_P.1 R26_P.1 R28_P.2 | length 658.1
  Top Layer w20: R28_P.2@1845,1789 1841.69,1789 1810,1757.31 1810,1594 v1(1870,1534) 1945,1609 v1(2095,1609)
  Bottom Layer w20: v1(1870,1534) 1870,1582.31 D14_P.1@1871.69,1584 ; v1(2095,1609) R26_P.1@2095,1664
NetD14_P_2: D14_P.2 D16_P.2 | length 70
  Bottom Layer w20: D14_P.2@1958.31,1584 D16_P.2@1958.31,1654
NetD17_P_1: D17_P.1 Q4_P.3 | length 122.3
  Bottom Layer w20: Q4_P.3@5010,2198.25 5056.06,2198.25 D17_P.1@5110,2252.19
NetD18_P_2: D18_P.2 R42_P.2 U5_P.7 | length 625.9
  Bottom Layer w20: D18_P.2@4616.69,1939 4570,1985.69 4570,2051.11 4507.11,2114 U5_P.7@4472.72,2114 4440,2114 4420,2134 4420,2184 4433.27,2197.27 4480.87,2197.27 4516.1,2232.5 R42_P.2@4660,2232.5
NetD19_P_1: D19_P.1 Q5_P.3 | length 681.4
  Top Layer w20: D19_P.1@5260,1529.94 v1(5260,1584)
  Bottom Layer w20: Q5_P.3@4707.24,1764 5080,1764 v1(5260,1584)
NetD19_P_2: D19_P.2 R36_P.1 | length 693.7
  Top Layer w20: D19_P.2@5260,1648.06 v1(5260,1709)
  Bottom Layer w20: R36_P.1@4691.5,1864 5105,1864 v1(5260,1709)
NetD20_P_2: D20_P.2 L8_P.2 U7_P.1 U7_P.24
NetD22_P_1: D22_P.1 L10_P.1 U7_P.13 U7_P.14
NetD23_P_1: D23_P.1 R56_P.1 | length 91.7
  Bottom Layer w30: R56_P.1@3210,2404 D23_P.1@3210,2495.69
NetD26_P_1: D26_P.1 D27_P.2 R58_P.1 | length 175.4
  Top Layer w20: D27_P.2@4950.94,544 4950.94,506.56 R58_P.1@4998.5,459 4996.69,457.19 D26_P.1@4996.69,389
NetD27_P_1: D27_P.1 U10_P.4 | length 825.9
  Top Layer w10: U10_P.4@4664.53,809.47 4664.53,785.57 4666.49,783.6 4684.6,783.6 v2(4685,784) ; D27_P.1@5069.06,544 5109,544 5195,630 v1(5195,695)
  Layer 2 w10: v2(4685,784) 4868.86,784 4957.86,695 5190,695 5195,690 v1(5195,695)
NetD29_P_2: D29_P.2 D31_P.1 | length 175.9
  Top Layer w20: D31_P.1@5069.06,644 v2(5145,644)
  Bottom Layer w10: D29_P.2@5053.31,664 5073.31,644 v2(5145,644)
NetD30_P_1: D30_P.1 R64_P.2 | length 126.8
  Top Layer w10: D30_P.1@4295.94,270 4337.5,311.55 v2(4337.5,324)
  Bottom Layer w15: R64_P.2@4286.5,324 4289,321.5 4337.5,321.5 4338.75,322.75 v2(4337.5,324)
NetD31_P_2: D31_P.2 R68_P.2 | length 150.9
  Top Layer w10: D31_P.2@4973.7,644 D31_P.2@4950.94,644 v2(5010,645)
  Bottom Layer w10: v2(5010,645) 5010,620.5 R68_P.2@5041.5,589
NetD32_P_2: D32_P.2 L15_P.2 U12_P.1 U12_P.15 U12_P.16
NetD33_P_1: D33_P.1 R79_P.2 | length 109.4
  Top Layer w20: R79_P.2@4191.5,764 D33_P.1@4300.94,764
NetD34_1: D34.1 R83.1 U14.1 | length 330.3
  Top Layer w50: 800,3062.09 1127.3,3062.09 U14.1@1129.39,3060
NetD46_1: D46.1 R147.2 U22.3 | length 136.1
  Top Layer w10: U22.3@4713.91,5030.38 4707.56,5036.74 4712.56,5041.74 D46.1@4712.56,5107.98 R147.2@4766.38,5107.98
NetD47_3: D47.3 D800.1 R192.1 | length 234.9
  Top Layer w20: R192.1@3724.33,3169.57 R192.1@3728.98,3174.21 ; R192.1@3739.21,3141.52 3739.21,3169.21 3745,3175 D47.3@3820,3175 ; D47.3@3840.53,3178.94 D47.3@3848.43,3171.04 3848.43,3190.89 D800.1@3909.53,3252
NetD48_3: D48.3 D801.1 R195.1 | length 247.3
  Top Layer w20: R195.1@3727.09,3535 3780,3535 3791.26,3523.74 D48.3@3838.86,3523.74 3830.53,3532.07 3830.53,3553.55 3889.98,3613 D801.1@3903.53,3613
NetD49_3: D49.3 D802.1 R200.1 | length 244.4
  Top Layer w20: R200.1@3707.09,3895.31 3759.69,3895.31 3776.26,3878.74 D49.3@3828.86,3878.74 3828.86,3914.33 D802.1@3885.53,3971
NetD50_3: D50.3 D803.1 R203.1 | length 285.9
  Top Layer w20: v1@3750,4314.72 3816.86,4247.86 3824.74,4247.86 D50.3@3828.86,4243.74 3828.86,4278 3828.53,4278 D803.1@3887.53,4337
  Bottom Layer w20: R203.1@3703.09,4337 3733,4337 v1(3754,4316)
NetD51_1: D51.1 Q10.3 | length 93.9
  Top Layer w10: Q10.3@1828.72,3625.04 1888.78,3625.04 1898.82,3615 D51.1@1918.5,3615
NetD51_2: D51.2 R211.1 | length 112.5
  Top Layer w10: R211.1@1951.47,3715.04 1951.47,3683.53 1981.5,3653.5 D51.2@1981.5,3615
NetD52_1: D52.1 Q11.3 | length 93.3
  Top Layer w10: Q11.3@5209.41,3226.87 5295.67,3226.87 D52.1@5300.67,3221.87
NetD52_2: D52.2 R212.1 | length 79.8
  Top Layer w10: R212.1@5356.5,3145 5356.5,3214.7 D52.2@5363.66,3221.87
NetD53_1: D53.1 Q12.3 | length 84.8
  Top Layer w10: Q12.3@5207.24,3430 D53.1@5292.01,3430
NetD53_2: D53.2 R213.1 | length 84.1
  Top Layer w10: R213.1@5345,3510 5345,3440 D53.2@5355,3430
NetD54_1: D54.1 Q13.3 | length 96.6
  Top Layer w10: Q13.3@5156.93,3925.61 5185.04,3925.61 5194.74,3935.31 D54.1@5249.49,3935.31
NetD54_2: D54.2 R214.1 | length 85.4
  Top Layer w10: R214.1@5299.49,3855.31 5312.48,3868.31 D54.2@5312.48,3935.31
NetD55_1: D55.1 Q14.3 | length 98.4
  Top Layer w10: Q14.3@5152.44,4133.01 5177.44,4133.01 5195.14,4115.31 D55.1@5243.5,4115.31
NetD55_2: D55.2 R215.1 | length 84.1
  Top Layer w10: R215.1@5296.5,4195.31 5306.5,4185.31 D55.2@5306.5,4115.31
